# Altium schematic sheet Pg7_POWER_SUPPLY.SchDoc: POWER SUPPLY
size 431 x 279 mm; Date: Not shown in title block; ApprovedBy: Not shown in title block; CheckedBy: Not shown in title block; Author: Not shown in title block; CompanyName: Not shown in title block; Engineer: Not shown in title block; Organization: Not shown in title block; Address1: Not shown in title block; Address2: Not shown in title block; Address3: Not shown in title block; Address4: Not shown in title block; DocumentNumber: 7; Revision: Use project parameter SCH_Rev; SheetNumber: 7; SheetTotal: 9; PageSetup: Record=PageOptions|CenterHorizontal=True|CenterVertical=True|PrintScale=1.00|XCorrection=1.00|YCorrection=1.00|PrintKind=0|BorderSize=5000000|LeftOffset=0|BottomOffset=0|Orientation=2|PaperLength=1000|PaperWidth=1000|Scale=100|PaperSource=15|PrintQuality=600|MediaType=1|DitherType=10|PaperKind=Letter|PrintScaleMode=1
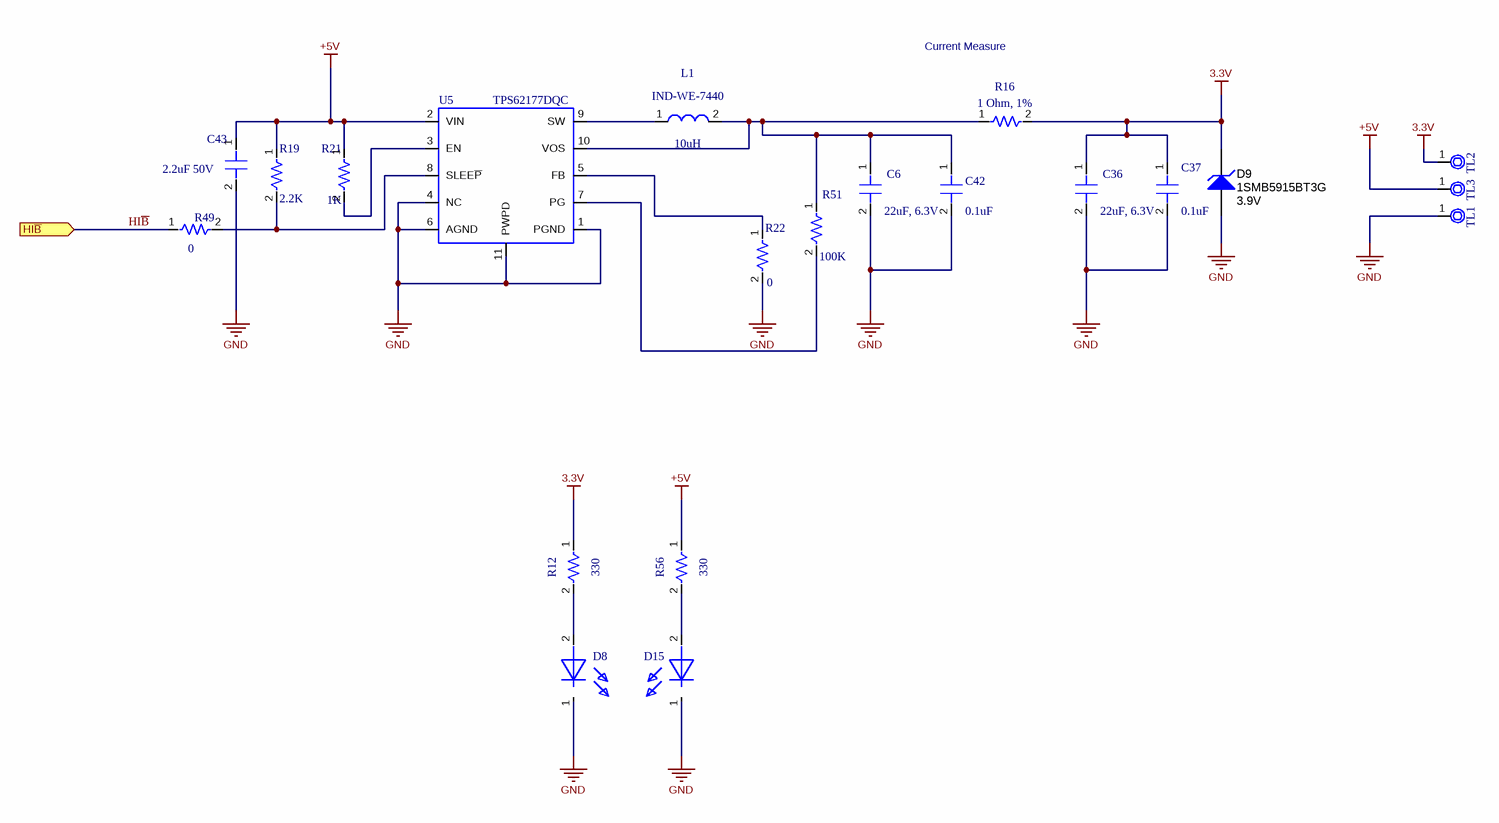
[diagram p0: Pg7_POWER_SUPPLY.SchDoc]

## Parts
C6  value 22uF, 6.3V  [0805]  (hidden comment: CAPC0805)
C36  value 22uF, 6.3V  [0805]  (hidden comment: CAPC0805)
C37  value 0.1uF  [0603]  (hidden comment: CAPC0603)
C42  value 0.1uF  [0603]  (hidden comment: CAPC0603)
C43  value 2.2uF 50V  [0805]  (hidden comment: CAPC0805)
D8  LED-0805  [DIOC0805N]  (value not drawn)
D9  1SMB5915BT3G  value 3.9V  [SMB]
D15  LED-0805  [DIOC0805N]  (value not drawn)
L1  IND-WE-7440  value 10uH  [IND_744029100]
R12  value 330  [0402]  (hidden comment: RESC0402)
R16  value 1 Ohm, 1%  [0603]  (hidden comment: RESC0603)
R19  value 2.2K  [0603]  (hidden comment: RESC0603)
R21  value 1K  [0603]  (hidden comment: RESC0603)
R22  value 0  [0603]  (hidden comment: RESC0603)
R49  value 0  [0603]  (hidden comment: RESC0603)
R51  value 100K  [0603]  (hidden comment: RESC0603)
R56  value 330  [0402]  (hidden comment: RESC0402)
TL1  TESTLOOP-100  [PAD70H39]  (value not drawn)
TL2  TESTLOOP-100  [PAD70H39]  (value not drawn)
TL3  TESTLOOP-100  [PAD70H39]  (value not drawn)
U5  TPS62177DQC  [DQC-10P]

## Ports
HI~{B}

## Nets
3.3V: C36.1 C37.1 D9.1(K) R12.1 R16.2 TL2.1
+5V: C43.1 R19.1 R21.1 R56.1 TL3.1 U5.2(VIN)
GND: C6.2 C36.2 C37.2 C42.2 C43.2 D8.1 D9.2(A) D15.1 R22.2 TL1.1 U5.1(PGND) U5.4(NC) U5.6(AGND) U5.11(PWPD)
HI~{B}: R49.1 ; port HI~{B}
NetC6_1: C6.1 C42.1 L1.2 R16.1 R51.1 U5.10(VOS)
NetD8_2: D8.2 R12.2
NetD15_2: D15.2 R56.2
NetL1_1: L1.1 U5.9(SW)
NetR19_2: R19.2 R49.2 U5.8(SLEE~{P})
NetR21_2: R21.2 U5.3(EN)
NetR22_1: R22.1 U5.5(FB)
NetR51_2: R51.2 U5.7(PG)

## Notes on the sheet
- Current Measure

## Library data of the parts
C6 = CAPC0805: Capacitor, 22uF 6.3V 20% X5R 0805; PartNumber: C2012X5R0J226M; GNUM: G10-C0805-C226-DCB; Description: Capacitor,Chip;2.00mm L X 1.25mm W X 1.10mm H; Geometry.Height: 1.1mm; PCBL.Component: CHP;CAPC;1800;2200;250;750;1050;1450;1100; PCBL.Process: F;N;50;50;200;100;200;250;350;-50;0
C36 = CAPC0805: Capacitor, 22uF 6.3V 20% X5R 0805; PartNumber: C2012X5R0J226M/1.25; GNUM: G10-C0805-C226-DCB; Description: Capacitor,Chip;2.00mm L X 1.25mm W X 1.10mm H; Geometry.Height: 1.1mm; PCBL.Component: CHP;CAPC;1800;2200;250;750;1050;1450;1100; PCBL.Process: F;N;50;50;200;100;200;250;350;-50;0
C37 C42 = CAPC0603: Capacitor, 0.1uF 50V, 20% 0603 X7R; Part Number: C1608X7R1H104M; GNUM: G10-C0603-C104-ACA; PCB DECAL: CAPC0603L
C43 = CAPC0805: Capacitor, 2.2uF 50V 10% X5R 0805; Part Number: C2012X5R1H225K; GNUM: G10-C0805-C225-ABB
D8 = LED-0805: LED, Green 565nm, Clear 0805 SMD; Manufacturer #1: LITE-ON; Part Number: LTST-C171GKT; Description: SMT LED IN 0805 PACK; GNUM: G14-D0805-GR00-AAA
D9 = 1SMB5915BT3G: Diode, Zener, 3.9V, 550mW, SMB; Manufacturer: ON Semiconductor; SymbolCreator: a0412235; U/M: EA; Power_W: 0.55; Vz_V: 3.9; Value1: 0.55W; RJA_CperW: 226
D15 = LED-0805: LED AMBER CLEAR 0805 SMD; Part Number: LTST-C170AKT; GNUM: G14-D0805-AMB0-AAA
L1 = IND-WE-7440: Inductor 10uH, SMD 2.8x2.8mm, 0.5A, 0.47 Ohm; Part Number: 744029100; GNUM: G12-SM2X2-I100-ADA; PCB DECAL: IND-WE-2M8
R12 R56 = RESC0402: Resistor, 330 ohm, 1/10W, 5%, 0402; Manufacturer #1: Generic; Part Number: RC0402FR-07330RL; Description: Resistor,Chip;1.00mm L X 0.5mm W X 0.35mm H; Geometry.Height: 0.35mm; PCBL.Component: CHP;RESC;1500;1700;150;400;700;950;600; PCBL.Process: F;N;50;50;200;100;200;250;350;-50;0; PCB DECAL: RESC0402N; GNUM: G11-R0402-3300-AAA
R16 = RESC0603: Resistor, 1 OHM 1/10W 1% 0603, Thick; Manufacturer #1: Generic; Part Number: ERJ-3RQF1R0V; PCB DECAL: RESC0603N; GNUM: G11-R0603-R010-ABA; Description: Resistor,Chip;1.60mm L X 0.83mm W X 0.60mm H; Geometry.Height: 0.6mm; PCBL.Component: CHP;RESC;1500;1700;150;400;700;950;600; PCBL.Process: F;N;50;50;200;100;200;250;350;-50;0; Tolerance: 5%
R19 = RESC0603: Resistor, 2.2K OHM 1/10W 5% 0603 SMD; Manufacturer #1: Generic; Part Number: CRCW06032K20JNEA; PCB DECAL: RESC0603N; GNUM: G11-R0603-R222-AAA; Description: Resistor,Chip;1.60mm L X 0.83mm W X 0.60mm H; Geometry.Height: 0.6mm; PCBL.Component: CHP;RESC;1500;1700;150;400;700;950;600; PCBL.Process: F;N;50;50;200;100;200;250;350;-50;0
R21 = RESC0603: Resistor, 1K Ohm, 1/10W, 5%, SMD, Thick; Manufacturer #1: Generic; Part Number: ERJ-3GEYJ102V; PCB DECAL: RESC0603N; GNUM: G11-R0603-R102-AAA; Description: Resistor,Chip;1.60mm L X 0.83mm W X 0.60mm H; Geometry.Height: 0.6mm; PCBL.Component: CHP;RESC;1500;1700;150;400;700;950;600; PCBL.Process: F;N;50;50;200;100;200;250;350;-50;0
R22 R49 = RESC0603: Resistor, 0 OHM 1/10W 0603 SMD; Manufacturer #1: Generic; Part Number: ERJ-3GEY0R00V; PCB DECAL: RESC0603N; GNUM: G11-R0603-R000-AAA; Description: Resistor,Chip;1.60mm L X 0.83mm W X 0.60mm H; Geometry.Height: 0.6mm; PCBL.Component: CHP;RESC;1500;1700;150;400;700;950;600; PCBL.Process: F;N;50;50;200;100;200;250;350;-50;0; Tolerance: 5%
R51 = RESC0603: Resistor, 100K OHM 1/10W 5% 0603 Thick; Part Number: ERJ-3GEYJ104V; PCB DECAL: RESC0603N; GNUM: G11-R0603-R104-AAA
TL1-TL3 = TESTLOOP-100: Terminal, Test Point Miniature Loop, Red, T-Hole; Part Number: 5000; Manufacturer #1: Keystone Electronics; Description: Test loop, Miniature White, Through-hole; GNUM: G20-K5000-TP00-AAA
U5 = TPS62177DQC: Regulator, Step Down  3.3V, 0.5A; GNUM: G51-DQC10-2177-AAA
